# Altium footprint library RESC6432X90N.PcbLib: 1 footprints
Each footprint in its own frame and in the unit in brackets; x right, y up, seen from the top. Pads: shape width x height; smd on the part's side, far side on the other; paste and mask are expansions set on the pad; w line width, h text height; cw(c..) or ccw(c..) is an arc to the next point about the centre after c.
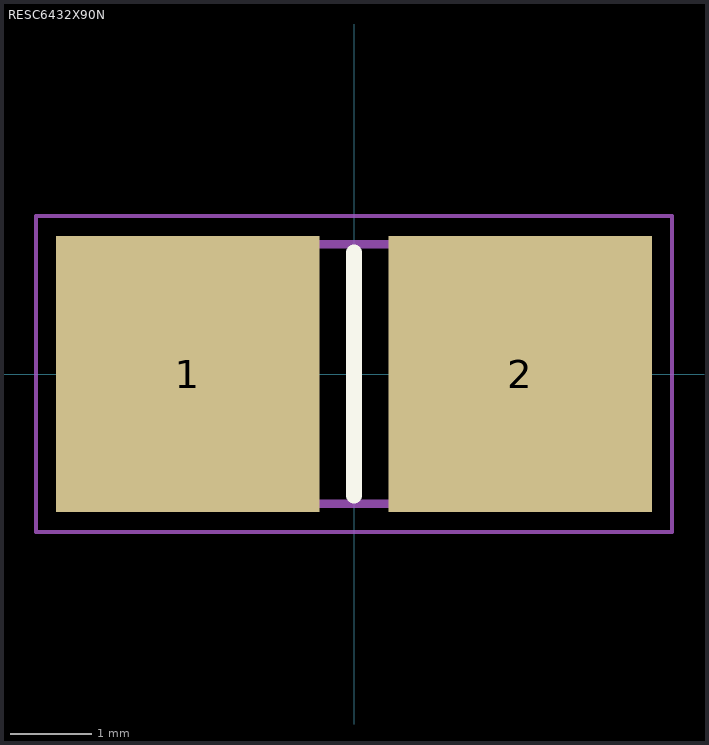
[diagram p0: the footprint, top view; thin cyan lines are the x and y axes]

## RESC6432X90N [mm]
pads (2):
  rect 3.25x3.4 smd: 1(-2.05,0) 2(2.05,0)
Top Overlay:
  lines w0.2: 0,-1.5 0,1.5
Mechanical 15:
  lines w0.1: -3.2,-1.6 3.2,-1.6 3.2,1.6 -3.2,1.6 -3.2,-1.6
Mechanical 20:
  lines w0.05: -3.925,-1.95 3.925,-1.95 3.925,1.95 -3.925,1.95 -3.925,-1.95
